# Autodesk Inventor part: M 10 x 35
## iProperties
IsCustomPart: 0
Created: 2009-02
Part Number: M 10 x 35
Material: 강, 연강
Description: 6각머리 태핑 나사
Document SubType Name: Modeling
Standard: KS B 1003
Designer: KYOUNG IL JANG
Standards Organization: KS
Language: ko-KR
Size Designation: M 10 x 35
Categories: <MemberInstance><Categories><Category DisplayName="조임쇠" InternalName="e4da775c-781d-43d5-af7c-5136215cf5a6" Mnemonic="FSTN"><Category DisplayName="볼트" InternalN
Density: 7.86 g/cm^3
Mass: 34.5961 g
Surface Area: 21.1658 cm^2
Volume: 4.40154 cm^3
Author: KYOUNG IL JANG
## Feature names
1. Fillet2
